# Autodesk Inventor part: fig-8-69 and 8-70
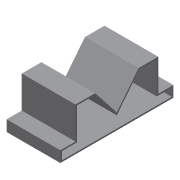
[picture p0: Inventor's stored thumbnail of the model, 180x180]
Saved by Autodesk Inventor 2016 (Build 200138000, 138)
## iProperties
Shininess: 77.0
Length Units: 11269
Angle Units: 11279
Time Units: 11290
Mass Units: 11283
Length Display Precision: 3
Angle Display Precision: 2
Created: 2002-01
Part Number: fig-8-69 and 8-70
Document SubType Name: Modeling
Designer: ***
Density: 1 g/cm^3
Material: Generic
Appearance: Default
Density: 0.0
Volumn: 0.0
Area: 0.0
PropertySet Name: Model Information
Control State: 0
Master: False
Checked Out: False
Author: ***
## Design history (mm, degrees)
node "Sketch1"
sketch "Sketch2"
  geometry: L1 (0, 0)-(-14.184, 17.961); L2 (-14.184, 17.961)-(-26.987, 17.961); L3 (-26.987, 17.961)-(-26.987, -2.947); L4 (-26.987, -2.947)-(-36.842, -2.947); L5 (-36.842, -2.947)-(-36.842, -10.132); L6 (26.987, 17.961)-(26.987, -2.947); L7 (14.184, 17.961)-(26.987, 17.961); L8 (26.987, -2.947)-(36.842, -2.947); L9 (36.842, -10.132)-(-36.842, -10.132); L10 (36.842, -2.947)-(36.842, -10.132); L11 (0, 0)-(14.184, 17.961)
  constraints: 22 end point, 2 horizontal, 2 parallel, 1 perpendicular
extrude "Extrusion1" new body sketch "Sketch2" distance "d0" = 35; taper "d1" = 0 deg
shell "Shell3" dims "d13" = 1
body "Solid1"
